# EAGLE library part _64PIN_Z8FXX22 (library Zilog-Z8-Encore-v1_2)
Z8 Encore, LQFP-64 Package
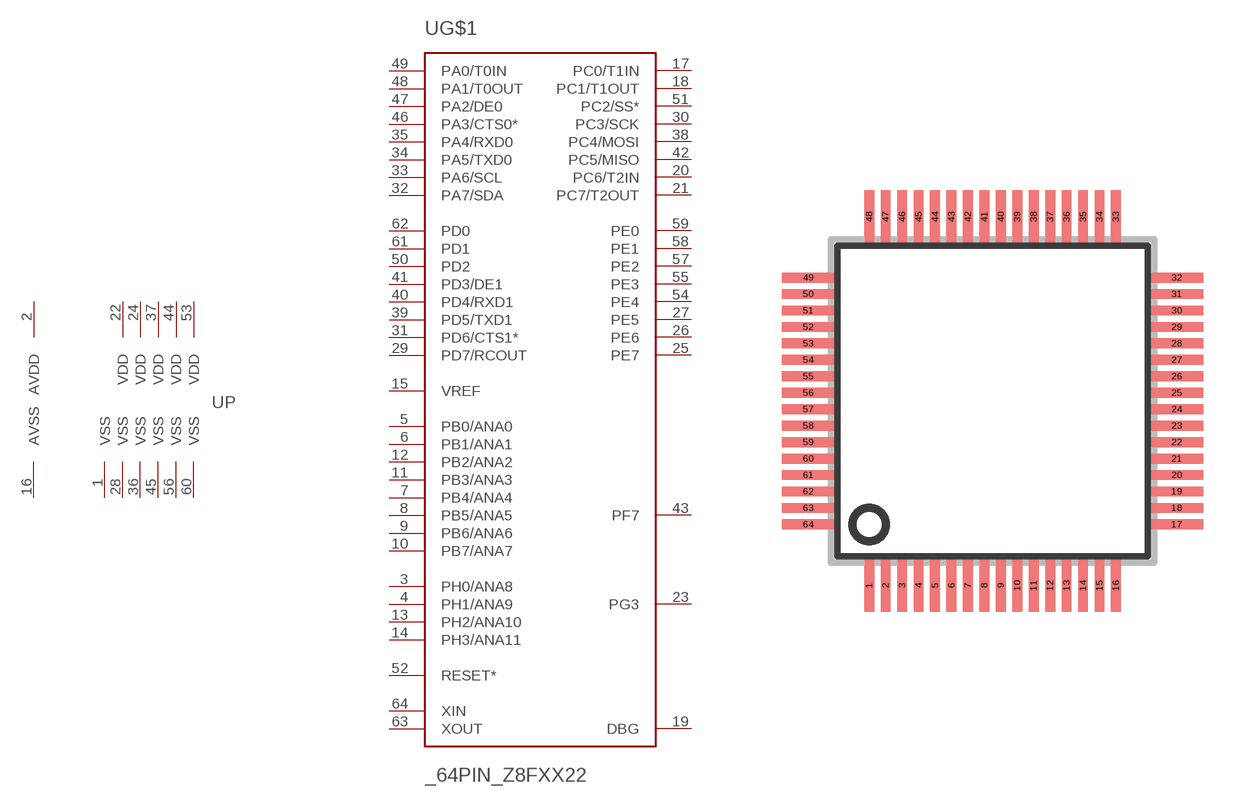
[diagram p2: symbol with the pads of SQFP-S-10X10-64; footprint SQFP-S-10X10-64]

Designator prefix U; gates G$1=Z8FXX22 P=PWR_64-PIN

## _64PIN_Z8FXX22AR  [SQFP-S-10X10-64]
1  P:VSS  pwr
2  P:AVDD  pwr
3  G$1:PH0/ANA8
4  G$1:PH1/ANA9
5  G$1:PB0/ANA0
6  G$1:PB1/ANA1
7  G$1:PB4/ANA4
8  G$1:PB5/ANA5
9  G$1:PB6/ANA6
10  G$1:PB7/ANA7
11  G$1:PB3/ANA3
12  G$1:PB2/ANA2
13  G$1:PH2/ANA10
14  G$1:PH3/ANA11
15  G$1:VREF  pas
16  P:AVSS  pwr
17  G$1:PC0/T1IN
18  G$1:PC1/T1OUT
19  G$1:DBG
20  G$1:PC6/T2IN
21  G$1:PC7/T2OUT
22  P:VDD  pwr
23  G$1:PG3
24  P:VDD  pwr
25  G$1:PE7
26  G$1:PE6
27  G$1:PE5
28  P:VSS  pwr
29  G$1:PD7/RCOUT
30  G$1:PC3/SCK
31  G$1:PD6/CTS1*
32  G$1:PA7/SDA
33  G$1:PA6/SCL
34  G$1:PA5/TXD0
35  G$1:PA4/RXD0
36  P:VSS  pwr
37  P:VDD  pwr
38  G$1:PC4/MOSI
39  G$1:PD5/TXD1
40  G$1:PD4/RXD1
41  G$1:PD3/DE1
42  G$1:PC5/MISO
43  G$1:PF7
44  P:VDD  pwr
45  P:VSS  pwr
46  G$1:PA3/CTS0*
47  G$1:PA2/DE0
48  G$1:PA1/T0OUT
49  G$1:PA0/T0IN
50  G$1:PD2
51  G$1:PC2/SS*
52  G$1:RESET*  in
53  P:VDD  pwr
54  G$1:PE4
55  G$1:PE3
56  P:VSS  pwr
57  G$1:PE2
58  G$1:PE1
59  G$1:PE0
60  P:VSS  pwr
61  G$1:PD1
62  G$1:PD0
63  G$1:XOUT  out
64  G$1:XIN  in

## Footprint SQFP-S-10X10-64 (pad centres in mm)
LQFP64 shrink quad flat pack, square
smd 0.3 x 1.6: 1 -3.75,-5.6; 2 -3.25,-5.6; 3 -2.75,-5.6; 4 -2.25,-5.6; 5 -1.75,-5.6; 6 -1.25,-5.6; 7 -0.75,-5.6; 8 -0.25,-5.6; 9 0.25,-5.6; 10 0.75,-5.6; 11 1.25,-5.6; 12 1.75,-5.6; 13 2.25,-5.6; 14 2.75,-5.6; 15 3.25,-5.6; 16 3.75,-5.6; 33 3.75,5.6; 34 3.25,5.6; 35 2.75,5.6; 36 2.25,5.6; 37 1.75,5.6; 38 1.25,5.6; 39 0.75,5.6; 40 0.25,5.6; 41 -0.25,5.6; 42 -0.75,5.6; 43 -1.25,5.6; 44 -1.75,5.6; 45 -2.25,5.6; 46 -2.75,5.6; 47 -3.25,5.6; 48 -3.75,5.6
smd 1.6 x 0.3: 17 5.6,-3.75; 18 5.6,-3.25; 19 5.6,-2.75; 20 5.6,-2.25; 21 5.6,-1.75; 22 5.6,-1.25; 23 5.6,-0.75; 24 5.6,-0.25; 25 5.6,0.25; 26 5.6,0.75; 27 5.6,1.25; 28 5.6,1.75; 29 5.6,2.25; 30 5.6,2.75; 31 5.6,3.25; 32 5.6,3.75; 49 -5.6,3.75; 50 -5.6,3.25; 51 -5.6,2.75; 52 -5.6,2.25; 53 -5.6,1.75; 54 -5.6,1.25; 55 -5.6,0.75; 56 -5.6,0.25; 57 -5.6,-0.25; 58 -5.6,-0.75; 59 -5.6,-1.25; 60 -5.6,-1.75; 61 -5.6,-2.25; 62 -5.6,-2.75; 63 -5.6,-3.25; 64 -5.6,-3.75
